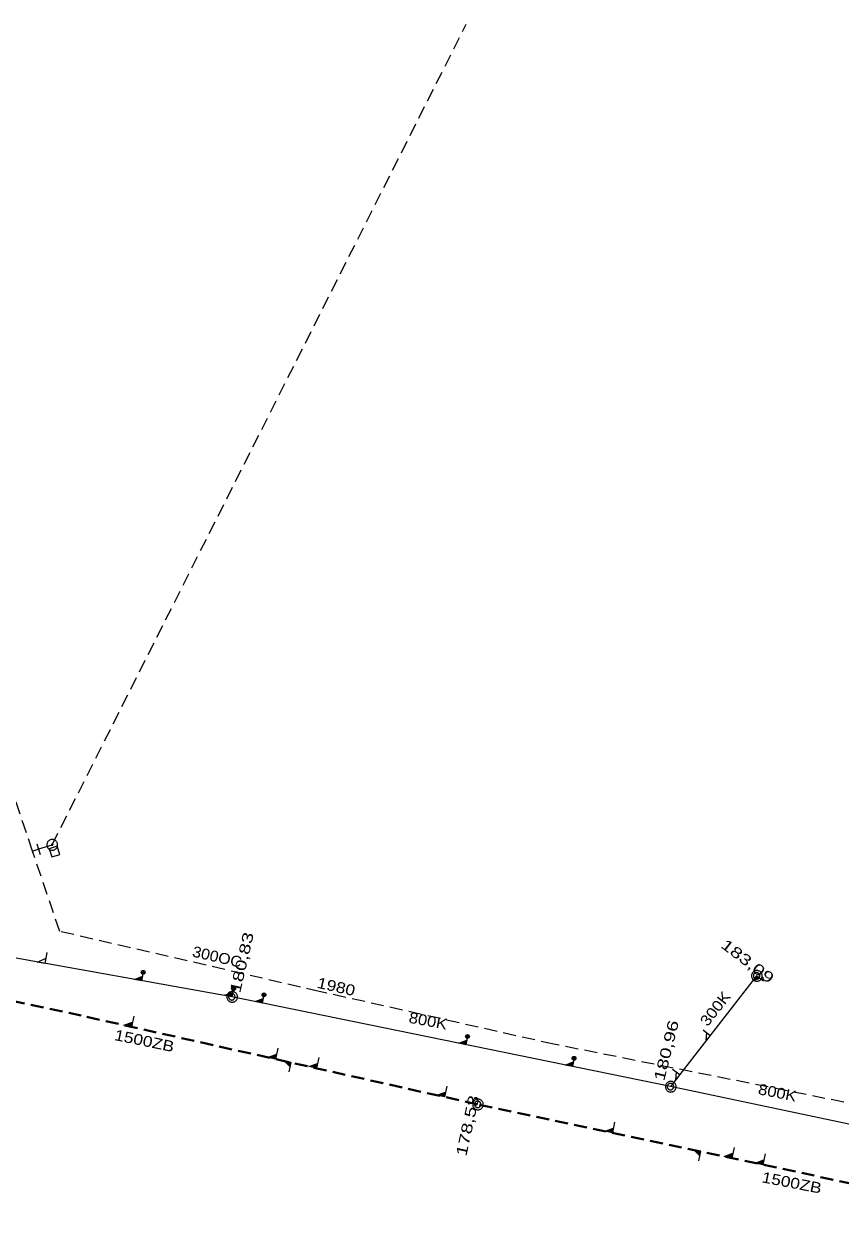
# Model space of a CAD drawing. Extents: x -740851 to -738888, y -1041382 to -1040235.
# Drawn here: x -740295.1 to -740219.2, y -1040431.1 to -1040319 of the extents above; entities that cross this region are included whole.
import ezdxf

# ---------------------------------------------------------------- set-up
doc = ezdxf.new("R2010")
doc.units = 0
doc.header["$LTSCALE"] = 0.4
doc.linetypes.add('MEDIUM_DASHED', pattern=[4.5, 3, -1.5])
for name, color, linetype, lineweight in [('18', 7, 'Continuous', 13), ('38', 7, 'Continuous', 13), ('39', 7, 'MEDIUM_DASHED', 13), ('8', 7, 'Continuous', 13)]:
    doc.layers.add(name, color=color, linetype=linetype, lineweight=lineweight)

msp = doc.modelspace()

# ---------------------------------------------------------------- linework, layer by layer
at = {"layer": '18', "lineweight": 25}
for p, q in [((-740275.79, -1040409.29), (-740318.03, -1040401.76)), ((-740227.03, -1040407.34), (-740235.03, -1040417.63)), ((-740235.03, -1040417.63), (-740275.79, -1040409.29)), ((-740216.38, -1040421.57), (-740235.03, -1040417.63))]:
    msp.add_line(p, q, dxfattribs=at)
at = {"layer": '18', "linetype": 'MEDIUM_DASHED', "lineweight": 40}
msp.add_line((-740197.01, -1040431.12), (-740252.95, -1040419.28), dxfattribs=at)
at = {"layer": '18'}
for points in [[(-740292.997, -1040405.188), (-740293.175, -1040406.188), (-740293.888, -1040406.061), (-740293.094, -1040405.737)], [(-740284.002, -1040406.841), (-740284.172, -1040407.793), (-740284.852, -1040407.672), (-740284.096, -1040407.364)], [(-740284.163, -1040407.45), (-740284.212, -1040407.728), (-740284.646, -1040407.65), (-740284.158, -1040407.451)], [(-740284.231, -1040407.541), (-740284.255, -1040407.68), (-740284.478, -1040407.64), (-740284.226, -1040407.542)], [(-740226.387, -1040407.84), (-740227.03, -1040407.34), (-740227.387, -1040407.799), (-740226.74, -1040407.566)], [(-740226.831, -1040407.549), (-740227.018, -1040407.404), (-740227.246, -1040407.697), (-740226.828, -1040407.546)], [(-740226.924, -1040407.53), (-740227.018, -1040407.458), (-740227.135, -1040407.608), (-740226.922, -1040407.527)], [(-740275.596, -1040408.356), (-740275.787, -1040409.288), (-740276.453, -1040409.152), (-740275.701, -1040408.868)], [(-740275.769, -1040408.951), (-740275.825, -1040409.223), (-740276.25, -1040409.136), (-740275.765, -1040408.952)], [(-740275.838, -1040409.039), (-740275.866, -1040409.175), (-740276.084, -1040409.13), (-740275.834, -1040409.04)], [(-740272.773, -1040408.933), (-740272.964, -1040409.866), (-740273.63, -1040409.73), (-740272.878, -1040409.445)], [(-740272.946, -1040409.529), (-740273.002, -1040409.8), (-740273.427, -1040409.713), (-740272.942, -1040409.53)], [(-740273.015, -1040409.617), (-740273.043, -1040409.752), (-740273.261, -1040409.708), (-740273.011, -1040409.618)], [(-740284.885, -1040411.083), (-740285.109, -1040412.083), (-740285.822, -1040411.923), (-740285.008, -1040411.632)], [(-740285.083, -1040411.72), (-740285.148, -1040412.011), (-740285.604, -1040411.909), (-740285.078, -1040411.721)], [(-740285.159, -1040411.813), (-740285.191, -1040411.959), (-740285.425, -1040411.907), (-740285.154, -1040411.814)], [(-740232.007, -1040412.355), (-740231.337, -1040412.876), (-740231.709, -1040413.355), (-740231.639, -1040412.641)], [(-740253.854, -1040412.804), (-740254.045, -1040413.737), (-740254.71, -1040413.601), (-740253.959, -1040413.316)], [(-740254.027, -1040413.4), (-740254.082, -1040413.671), (-740254.507, -1040413.584), (-740254.022, -1040413.401)], [(-740254.096, -1040413.488), (-740254.124, -1040413.623), (-740254.342, -1040413.579), (-740254.091, -1040413.489)], [(-740271.516, -1040414.074), (-740271.739, -1040415.074), (-740272.453, -1040414.914), (-740271.638, -1040414.623)], [(-740271.713, -1040414.711), (-740271.778, -1040415.002), (-740272.234, -1040414.9), (-740271.708, -1040414.712)], [(-740271.789, -1040414.804), (-740271.822, -1040414.95), (-740272.056, -1040414.898), (-740271.784, -1040414.806)], [(-740270.467, -1040416.267), (-740270.274, -1040415.404), (-740270.889, -1040415.267), (-740270.361, -1040415.793)], [(-740270.387, -1040415.697), (-740270.33, -1040415.446), (-740270.723, -1040415.358), (-740270.382, -1040415.698)], [(-740270.412, -1040415.596), (-740270.383, -1040415.47), (-740270.585, -1040415.425), (-740270.407, -1040415.597)], [(-740267.71, -1040414.925), (-740267.933, -1040415.925), (-740268.647, -1040415.766), (-740267.832, -1040415.474)], [(-740267.907, -1040415.563), (-740267.973, -1040415.854), (-740268.428, -1040415.752), (-740267.903, -1040415.564)], [(-740267.983, -1040415.656), (-740268.016, -1040415.802), (-740268.25, -1040415.749), (-740267.979, -1040415.657)], [(-740243.953, -1040414.83), (-740244.144, -1040415.763), (-740244.81, -1040415.627), (-740244.058, -1040415.342)], [(-740244.126, -1040415.426), (-740244.182, -1040415.697), (-740244.607, -1040415.61), (-740244.121, -1040415.426)], [(-740244.195, -1040415.514), (-740244.223, -1040415.649), (-740244.441, -1040415.605), (-740244.19, -1040415.514)], [(-740234.838, -1040415.996), (-740234.168, -1040416.517), (-740234.54, -1040416.996), (-740234.47, -1040416.282)], [(-740255.804, -1040417.589), (-740256.028, -1040418.589), (-740256.741, -1040418.429), (-740255.927, -1040418.138)], [(-740256.002, -1040418.226), (-740256.067, -1040418.517), (-740256.523, -1040418.415), (-740255.997, -1040418.227)], [(-740256.078, -1040418.32), (-740256.11, -1040418.465), (-740256.344, -1040418.413), (-740256.073, -1040418.321)], [(-740240.218, -1040420.928), (-740240.429, -1040421.928), (-740241.143, -1040421.777), (-740240.334, -1040421.477)], [(-740240.408, -1040421.566), (-740240.469, -1040421.857), (-740240.925, -1040421.76), (-740240.403, -1040421.567)], [(-740240.482, -1040421.66), (-740240.513, -1040421.805), (-740240.747, -1040421.756), (-740240.477, -1040421.661)], [(-740232.393, -1040424.539), (-740232.21, -1040423.67), (-740232.829, -1040423.539), (-740232.292, -1040424.062)], [(-740232.32, -1040423.965), (-740232.266, -1040423.712), (-740232.662, -1040423.628), (-740232.315, -1040423.966)], [(-740232.346, -1040423.864), (-740232.319, -1040423.738), (-740232.522, -1040423.695), (-740232.342, -1040423.865)], [(-740229.114, -1040423.278), (-740229.325, -1040424.278), (-740230.039, -1040424.127), (-740229.23, -1040423.827)], [(-740229.304, -1040423.916), (-740229.365, -1040424.207), (-740229.821, -1040424.111), (-740229.299, -1040423.917)], [(-740229.378, -1040424.01), (-740229.409, -1040424.155), (-740229.643, -1040424.106), (-740229.373, -1040424.011)], [(-740226.228, -1040423.889), (-740226.439, -1040424.889), (-740227.153, -1040424.738), (-740226.344, -1040424.438)], [(-740226.418, -1040424.527), (-740226.479, -1040424.818), (-740226.935, -1040424.721), (-740226.413, -1040424.528)], [(-740226.492, -1040424.621), (-740226.523, -1040424.766), (-740226.757, -1040424.717), (-740226.487, -1040424.622)]]:
    msp.add_lwpolyline(points, dxfattribs=at)
for points in [[(-740226.5, -1040407.35), (-740226.51, -1040407.3), (-740226.51, -1040407.25), (-740226.53, -1040407.2), (-740226.55, -1040407.15), (-740226.57, -1040407.1), (-740226.6, -1040407.06), (-740226.63, -1040407.02), (-740226.67, -1040406.98), (-740226.71, -1040406.95), (-740226.75, -1040406.92), (-740226.8, -1040406.9), (-740226.85, -1040406.88), (-740226.9, -1040406.86), (-740226.95, -1040406.86), (-740227, -1040406.85), (-740227.05, -1040406.86), (-740227.1, -1040406.86), (-740227.15, -1040406.88), (-740227.2, -1040406.9), (-740227.25, -1040406.92), (-740227.29, -1040406.95), (-740227.33, -1040406.98), (-740227.37, -1040407.02), (-740227.4, -1040407.06), (-740227.43, -1040407.1), (-740227.45, -1040407.15), (-740227.47, -1040407.2), (-740227.49, -1040407.25), (-740227.49, -1040407.3), (-740227.5, -1040407.35), (-740227.49, -1040407.4), (-740227.49, -1040407.45), (-740227.47, -1040407.5), (-740227.45, -1040407.55), (-740227.43, -1040407.6), (-740227.4, -1040407.64), (-740227.37, -1040407.68), (-740227.33, -1040407.72), (-740227.29, -1040407.75), (-740227.25, -1040407.78), (-740227.2, -1040407.8), (-740227.15, -1040407.82), (-740227.1, -1040407.84), (-740227.05, -1040407.84), (-740227, -1040407.85), (-740226.95, -1040407.84), (-740226.9, -1040407.84), (-740226.85, -1040407.82), (-740226.8, -1040407.8), (-740226.75, -1040407.78), (-740226.71, -1040407.75), (-740226.67, -1040407.72), (-740226.63, -1040407.68), (-740226.6, -1040407.64), (-740226.57, -1040407.6), (-740226.55, -1040407.55), (-740226.53, -1040407.5), (-740226.51, -1040407.45), (-740226.51, -1040407.4)], [(-740226.73, -1040407.34), (-740226.73, -1040407.31), (-740226.736, -1040407.28), (-740226.742, -1040407.25), (-740226.754, -1040407.22), (-740226.772, -1040407.19), (-740226.79, -1040407.166), (-740226.808, -1040407.142), (-740226.832, -1040407.118), (-740226.856, -1040407.1), (-740226.88, -1040407.082), (-740226.91, -1040407.064), (-740226.94, -1040407.052), (-740226.97, -1040407.046), (-740227, -1040407.04), (-740227.03, -1040407.04), (-740227.06, -1040407.04), (-740227.09, -1040407.046), (-740227.12, -1040407.052), (-740227.15, -1040407.064), (-740227.18, -1040407.082), (-740227.204, -1040407.1), (-740227.228, -1040407.118), (-740227.252, -1040407.142), (-740227.27, -1040407.166), (-740227.288, -1040407.19), (-740227.306, -1040407.22), (-740227.318, -1040407.25), (-740227.324, -1040407.28), (-740227.33, -1040407.31), (-740227.33, -1040407.34), (-740227.33, -1040407.37), (-740227.324, -1040407.4), (-740227.318, -1040407.43), (-740227.306, -1040407.46), (-740227.288, -1040407.49), (-740227.27, -1040407.514), (-740227.252, -1040407.538), (-740227.228, -1040407.562), (-740227.204, -1040407.58), (-740227.18, -1040407.598), (-740227.15, -1040407.616), (-740227.12, -1040407.628), (-740227.09, -1040407.634), (-740227.06, -1040407.64), (-740227.03, -1040407.64), (-740227, -1040407.64), (-740226.97, -1040407.634), (-740226.94, -1040407.628), (-740226.91, -1040407.616), (-740226.88, -1040407.598), (-740226.856, -1040407.58), (-740226.832, -1040407.562), (-740226.808, -1040407.538), (-740226.79, -1040407.514), (-740226.772, -1040407.49), (-740226.754, -1040407.46), (-740226.742, -1040407.43), (-740226.736, -1040407.4), (-740226.73, -1040407.37)], [(-740275.26, -1040409.3), (-740275.27, -1040409.25), (-740275.27, -1040409.2), (-740275.29, -1040409.15), (-740275.31, -1040409.1), (-740275.33, -1040409.05), (-740275.36, -1040409.01), (-740275.39, -1040408.97), (-740275.43, -1040408.93), (-740275.47, -1040408.9), (-740275.51, -1040408.87), (-740275.56, -1040408.85), (-740275.61, -1040408.83), (-740275.66, -1040408.81), (-740275.71, -1040408.81), (-740275.76, -1040408.8), (-740275.81, -1040408.81), (-740275.86, -1040408.81), (-740275.91, -1040408.83), (-740275.96, -1040408.85), (-740276.01, -1040408.87), (-740276.05, -1040408.9), (-740276.09, -1040408.93), (-740276.13, -1040408.97), (-740276.16, -1040409.01), (-740276.19, -1040409.05), (-740276.21, -1040409.1), (-740276.23, -1040409.15), (-740276.25, -1040409.2), (-740276.25, -1040409.25), (-740276.26, -1040409.3), (-740276.25, -1040409.35), (-740276.25, -1040409.4), (-740276.23, -1040409.45), (-740276.21, -1040409.5), (-740276.19, -1040409.55), (-740276.16, -1040409.59), (-740276.13, -1040409.63), (-740276.09, -1040409.67), (-740276.05, -1040409.7), (-740276.01, -1040409.73), (-740275.96, -1040409.75), (-740275.91, -1040409.77), (-740275.86, -1040409.79), (-740275.81, -1040409.79), (-740275.76, -1040409.8), (-740275.71, -1040409.79), (-740275.66, -1040409.79), (-740275.61, -1040409.77), (-740275.56, -1040409.75), (-740275.51, -1040409.73), (-740275.47, -1040409.7), (-740275.43, -1040409.67), (-740275.39, -1040409.63), (-740275.36, -1040409.59), (-740275.33, -1040409.55), (-740275.31, -1040409.5), (-740275.29, -1040409.45), (-740275.27, -1040409.4), (-740275.27, -1040409.35)], [(-740275.49, -1040409.29), (-740275.49, -1040409.26), (-740275.496, -1040409.23), (-740275.502, -1040409.2), (-740275.514, -1040409.17), (-740275.532, -1040409.14), (-740275.55, -1040409.116), (-740275.568, -1040409.092), (-740275.592, -1040409.068), (-740275.616, -1040409.05), (-740275.64, -1040409.032), (-740275.67, -1040409.014), (-740275.7, -1040409.002), (-740275.73, -1040408.996), (-740275.76, -1040408.99), (-740275.79, -1040408.99), (-740275.82, -1040408.99), (-740275.85, -1040408.996), (-740275.88, -1040409.002), (-740275.91, -1040409.014), (-740275.94, -1040409.032), (-740275.964, -1040409.05), (-740275.988, -1040409.068), (-740276.012, -1040409.092), (-740276.03, -1040409.116), (-740276.048, -1040409.14), (-740276.066, -1040409.17), (-740276.078, -1040409.2), (-740276.084, -1040409.23), (-740276.09, -1040409.26), (-740276.09, -1040409.29), (-740276.09, -1040409.32), (-740276.084, -1040409.35), (-740276.078, -1040409.38), (-740276.066, -1040409.41), (-740276.048, -1040409.44), (-740276.03, -1040409.464), (-740276.012, -1040409.488), (-740275.988, -1040409.512), (-740275.964, -1040409.53), (-740275.94, -1040409.548), (-740275.91, -1040409.566), (-740275.88, -1040409.578), (-740275.85, -1040409.584), (-740275.82, -1040409.59), (-740275.79, -1040409.59), (-740275.76, -1040409.59), (-740275.73, -1040409.584), (-740275.7, -1040409.578), (-740275.67, -1040409.566), (-740275.64, -1040409.548), (-740275.616, -1040409.53), (-740275.592, -1040409.512), (-740275.568, -1040409.488), (-740275.55, -1040409.464), (-740275.532, -1040409.44), (-740275.514, -1040409.41), (-740275.502, -1040409.38), (-740275.496, -1040409.35), (-740275.49, -1040409.32)], [(-740234.5, -1040417.64), (-740234.51, -1040417.59), (-740234.51, -1040417.54), (-740234.53, -1040417.49), (-740234.55, -1040417.44), (-740234.57, -1040417.39), (-740234.6, -1040417.35), (-740234.63, -1040417.31), (-740234.67, -1040417.27), (-740234.71, -1040417.24), (-740234.75, -1040417.21), (-740234.8, -1040417.19), (-740234.85, -1040417.17), (-740234.9, -1040417.15), (-740234.95, -1040417.15), (-740235, -1040417.14), (-740235.05, -1040417.15), (-740235.1, -1040417.15), (-740235.15, -1040417.17), (-740235.2, -1040417.19), (-740235.25, -1040417.21), (-740235.29, -1040417.24), (-740235.33, -1040417.27), (-740235.37, -1040417.31), (-740235.4, -1040417.35), (-740235.43, -1040417.39), (-740235.45, -1040417.44), (-740235.47, -1040417.49), (-740235.49, -1040417.54), (-740235.49, -1040417.59), (-740235.5, -1040417.64), (-740235.49, -1040417.69), (-740235.49, -1040417.74), (-740235.47, -1040417.79), (-740235.45, -1040417.84), (-740235.43, -1040417.89), (-740235.4, -1040417.93), (-740235.37, -1040417.97), (-740235.33, -1040418.01), (-740235.29, -1040418.04), (-740235.25, -1040418.07), (-740235.2, -1040418.09), (-740235.15, -1040418.11), (-740235.1, -1040418.13), (-740235.05, -1040418.13), (-740235, -1040418.14), (-740234.95, -1040418.13), (-740234.9, -1040418.13), (-740234.85, -1040418.11), (-740234.8, -1040418.09), (-740234.75, -1040418.07), (-740234.71, -1040418.04), (-740234.67, -1040418.01), (-740234.63, -1040417.97), (-740234.6, -1040417.93), (-740234.57, -1040417.89), (-740234.55, -1040417.84), (-740234.53, -1040417.79), (-740234.51, -1040417.74), (-740234.51, -1040417.69)], [(-740234.73, -1040417.63), (-740234.73, -1040417.6), (-740234.736, -1040417.57), (-740234.742, -1040417.54), (-740234.754, -1040417.51), (-740234.772, -1040417.48), (-740234.79, -1040417.456), (-740234.808, -1040417.432), (-740234.832, -1040417.408), (-740234.856, -1040417.39), (-740234.88, -1040417.372), (-740234.91, -1040417.354), (-740234.94, -1040417.342), (-740234.97, -1040417.336), (-740235, -1040417.33), (-740235.03, -1040417.33), (-740235.06, -1040417.33), (-740235.09, -1040417.336), (-740235.12, -1040417.342), (-740235.15, -1040417.354), (-740235.18, -1040417.372), (-740235.204, -1040417.39), (-740235.228, -1040417.408), (-740235.252, -1040417.432), (-740235.27, -1040417.456), (-740235.288, -1040417.48), (-740235.306, -1040417.51), (-740235.318, -1040417.54), (-740235.324, -1040417.57), (-740235.33, -1040417.6), (-740235.33, -1040417.63), (-740235.33, -1040417.66), (-740235.324, -1040417.69), (-740235.318, -1040417.72), (-740235.306, -1040417.75), (-740235.288, -1040417.78), (-740235.27, -1040417.804), (-740235.252, -1040417.828), (-740235.228, -1040417.852), (-740235.204, -1040417.87), (-740235.18, -1040417.888), (-740235.15, -1040417.906), (-740235.12, -1040417.918), (-740235.09, -1040417.924), (-740235.06, -1040417.93), (-740235.03, -1040417.93), (-740235, -1040417.93), (-740234.97, -1040417.924), (-740234.94, -1040417.918), (-740234.91, -1040417.906), (-740234.88, -1040417.888), (-740234.856, -1040417.87), (-740234.832, -1040417.852), (-740234.808, -1040417.828), (-740234.79, -1040417.804), (-740234.772, -1040417.78), (-740234.754, -1040417.75), (-740234.742, -1040417.72), (-740234.736, -1040417.69), (-740234.73, -1040417.66)], [(-740252.42, -1040419.29), (-740252.43, -1040419.24), (-740252.43, -1040419.19), (-740252.45, -1040419.14), (-740252.47, -1040419.09), (-740252.49, -1040419.04), (-740252.52, -1040419), (-740252.55, -1040418.96), (-740252.59, -1040418.92), (-740252.63, -1040418.89), (-740252.67, -1040418.86), (-740252.72, -1040418.84), (-740252.77, -1040418.82), (-740252.82, -1040418.8), (-740252.87, -1040418.8), (-740252.92, -1040418.79), (-740252.97, -1040418.8), (-740253.02, -1040418.8), (-740253.07, -1040418.82), (-740253.12, -1040418.84), (-740253.17, -1040418.86), (-740253.21, -1040418.89), (-740253.25, -1040418.92), (-740253.29, -1040418.96), (-740253.32, -1040419), (-740253.35, -1040419.04), (-740253.37, -1040419.09), (-740253.39, -1040419.14), (-740253.41, -1040419.19), (-740253.41, -1040419.24), (-740253.42, -1040419.29), (-740253.41, -1040419.34), (-740253.41, -1040419.39), (-740253.39, -1040419.44), (-740253.37, -1040419.49), (-740253.35, -1040419.54), (-740253.32, -1040419.58), (-740253.29, -1040419.62), (-740253.25, -1040419.66), (-740253.21, -1040419.69), (-740253.17, -1040419.72), (-740253.12, -1040419.74), (-740253.07, -1040419.76), (-740253.02, -1040419.78), (-740252.97, -1040419.78), (-740252.92, -1040419.79), (-740252.87, -1040419.78), (-740252.82, -1040419.78), (-740252.77, -1040419.76), (-740252.72, -1040419.74), (-740252.67, -1040419.72), (-740252.63, -1040419.69), (-740252.59, -1040419.66), (-740252.55, -1040419.62), (-740252.52, -1040419.58), (-740252.49, -1040419.54), (-740252.47, -1040419.49), (-740252.45, -1040419.44), (-740252.43, -1040419.39), (-740252.43, -1040419.34)], [(-740252.65, -1040419.28), (-740252.65, -1040419.25), (-740252.656, -1040419.22), (-740252.662, -1040419.19), (-740252.674, -1040419.16), (-740252.692, -1040419.13), (-740252.71, -1040419.106), (-740252.728, -1040419.082), (-740252.752, -1040419.058), (-740252.776, -1040419.04), (-740252.8, -1040419.022), (-740252.83, -1040419.004), (-740252.86, -1040418.992), (-740252.89, -1040418.986), (-740252.92, -1040418.98), (-740252.95, -1040418.98), (-740252.98, -1040418.98), (-740253.01, -1040418.986), (-740253.04, -1040418.992), (-740253.07, -1040419.004), (-740253.1, -1040419.022), (-740253.124, -1040419.04), (-740253.148, -1040419.058), (-740253.172, -1040419.082), (-740253.19, -1040419.106), (-740253.208, -1040419.13), (-740253.226, -1040419.16), (-740253.238, -1040419.19), (-740253.244, -1040419.22), (-740253.25, -1040419.25), (-740253.25, -1040419.28), (-740253.25, -1040419.31), (-740253.244, -1040419.34), (-740253.238, -1040419.37), (-740253.226, -1040419.4), (-740253.208, -1040419.43), (-740253.19, -1040419.454), (-740253.172, -1040419.478), (-740253.148, -1040419.502), (-740253.124, -1040419.52), (-740253.1, -1040419.538), (-740253.07, -1040419.556), (-740253.04, -1040419.568), (-740253.01, -1040419.574), (-740252.98, -1040419.58), (-740252.95, -1040419.58), (-740252.92, -1040419.58), (-740252.89, -1040419.574), (-740252.86, -1040419.568), (-740252.83, -1040419.556), (-740252.8, -1040419.538), (-740252.776, -1040419.52), (-740252.752, -1040419.502), (-740252.728, -1040419.478), (-740252.71, -1040419.454), (-740252.692, -1040419.43), (-740252.674, -1040419.4), (-740252.662, -1040419.37), (-740252.656, -1040419.34), (-740252.65, -1040419.31)]]:
    msp.add_lwpolyline(points, close=True, dxfattribs=at)
at = {"layer": '18', "linetype": 'MEDIUM_DASHED', "lineweight": 40}
msp.add_lwpolyline([(-740252.95, -1040419.28), (-740289.78, -1040411.04), (-740299.021, -1040409.066), (-740306.23, -1040407.14)], dxfattribs=at)
at = {"layer": '18'}
for centre, radius in [((-740284.034, -1040407.016), 0.182), ((-740284.035, -1040407.015), 0.0901), ((-740275.632, -1040408.527), 0.179), ((-740275.633, -1040408.526), 0.0886), ((-740272.809, -1040409.105), 0.179), ((-740272.809, -1040409.103), 0.0886), ((-740253.89, -1040412.976), 0.179), ((-740253.89, -1040412.974), 0.0886), ((-740243.989, -1040415.002), 0.179), ((-740243.989, -1040415), 0.0886)]:
    msp.add_circle(centre, radius, dxfattribs=at)
at = {"layer": '38'}
for p, q in [((-740294.311, -1040395.753), (-740293.74, -1040395.56)), ((-740293.74, -1040395.56), (-740292.49, -1040395.17))]:
    msp.add_line(p, q, dxfattribs=at)
at = {"layer": '39'}
msp.add_line((-740292.49, -1040395.17), (-740254.007, -1040318.954), dxfattribs=at)
at = {"layer": '8'}
for p, q in [((-740293.558, -1040396.1), (-740293.896, -1040395.1)), ((-740292.539, -1040395.219), (-740292.439, -1040395.119)), ((-740292.539, -1040395.119), (-740292.439, -1040395.219)), ((-740292.539, -1040395.119), (-740292.539, -1040395.139)), ((-740292.539, -1040395.119), (-740292.519, -1040395.119)), ((-740292.539, -1040395.219), (-740292.539, -1040395.199)), ((-740292.539, -1040395.219), (-740292.519, -1040395.219)), ((-740292.439, -1040395.119), (-740292.459, -1040395.119)), ((-740292.439, -1040395.219), (-740292.459, -1040395.219)), ((-740292.439, -1040395.119), (-740292.439, -1040395.139)), ((-740292.439, -1040395.219), (-740292.439, -1040395.199))]:
    msp.add_line(p, q, dxfattribs=at)
at = {"layer": '8', "linetype": 'MEDIUM_DASHED', "lineweight": 25}
msp.add_lwpolyline([(-740213.61, -1040420.13), (-740245.88, -1040413.69), (-740267.67, -1040408.79), (-740291.79, -1040403.21), (-740294.311, -1040395.753), (-740297.337, -1040386.803)], dxfattribs=at)
at = {"layer": '8'}
for points in [[(-740292.001, -1040395.027), (-740292.025, -1040394.982), (-740292.04, -1040394.934), (-740292.074, -1040394.892), (-740292.108, -1040394.85), (-740292.143, -1040394.808), (-740292.183, -1040394.779), (-740292.224, -1040394.75), (-740292.274, -1040394.723), (-740292.322, -1040394.706), (-740292.369, -1040394.69), (-740292.423, -1040394.685), (-740292.477, -1040394.681), (-740292.531, -1040394.677), (-740292.579, -1040394.692), (-740292.63, -1040394.697), (-740292.675, -1040394.722), (-740292.723, -1040394.737), (-740292.765, -1040394.771), (-740292.807, -1040394.805), (-740292.849, -1040394.839), (-740292.878, -1040394.88), (-740292.908, -1040394.921), (-740292.934, -1040394.971), (-740292.951, -1040395.018), (-740292.968, -1040395.066), (-740292.972, -1040395.12), (-740292.976, -1040395.174), (-740292.98, -1040395.228), (-740292.965, -1040395.276), (-740292.96, -1040395.327), (-740292.935, -1040395.372), (-740292.92, -1040395.42), (-740292.886, -1040395.461), (-740292.852, -1040395.503), (-740292.818, -1040395.545), (-740292.777, -1040395.575), (-740292.736, -1040395.604), (-740292.686, -1040395.631), (-740292.639, -1040395.647), (-740292.591, -1040395.664), (-740292.537, -1040395.668), (-740292.483, -1040395.673), (-740292.429, -1040395.677), (-740292.382, -1040395.662), (-740292.331, -1040395.657), (-740292.286, -1040395.632), (-740292.238, -1040395.617), (-740292.196, -1040395.583), (-740292.154, -1040395.549), (-740292.112, -1040395.515), (-740292.082, -1040395.474), (-740292.053, -1040395.433), (-740292.027, -1040395.383), (-740292.01, -1040395.335), (-740291.993, -1040395.288), (-740291.989, -1040395.234), (-740291.984, -1040395.18), (-740291.98, -1040395.126), (-740291.995, -1040395.078)], [(-740292.533, -1040396.299), (-740291.771, -1040396.061), (-740292.009, -1040395.299), (-740292.771, -1040395.537)], [(-740292.439, -1040395.169), (-740292.439, -1040395.164), (-740292.44, -1040395.159), (-740292.441, -1040395.154), (-740292.443, -1040395.149), (-740292.446, -1040395.144), (-740292.449, -1040395.14), (-740292.452, -1040395.136), (-740292.456, -1040395.132), (-740292.46, -1040395.129), (-740292.464, -1040395.126), (-740292.469, -1040395.123), (-740292.474, -1040395.121), (-740292.479, -1040395.12), (-740292.484, -1040395.119), (-740292.489, -1040395.119), (-740292.494, -1040395.119), (-740292.499, -1040395.12), (-740292.504, -1040395.121), (-740292.509, -1040395.123), (-740292.514, -1040395.126), (-740292.518, -1040395.129), (-740292.522, -1040395.132), (-740292.526, -1040395.136), (-740292.529, -1040395.14), (-740292.532, -1040395.144), (-740292.535, -1040395.149), (-740292.537, -1040395.154), (-740292.538, -1040395.159), (-740292.539, -1040395.164), (-740292.539, -1040395.169), (-740292.539, -1040395.174), (-740292.538, -1040395.179), (-740292.537, -1040395.184), (-740292.535, -1040395.189), (-740292.532, -1040395.194), (-740292.529, -1040395.198), (-740292.526, -1040395.202), (-740292.522, -1040395.206), (-740292.518, -1040395.209), (-740292.514, -1040395.212), (-740292.509, -1040395.215), (-740292.504, -1040395.217), (-740292.499, -1040395.218), (-740292.494, -1040395.219), (-740292.489, -1040395.219), (-740292.484, -1040395.219), (-740292.479, -1040395.218), (-740292.474, -1040395.217), (-740292.469, -1040395.215), (-740292.464, -1040395.212), (-740292.46, -1040395.209), (-740292.456, -1040395.206), (-740292.452, -1040395.202), (-740292.449, -1040395.198), (-740292.446, -1040395.194), (-740292.443, -1040395.189), (-740292.441, -1040395.184), (-740292.44, -1040395.179), (-740292.439, -1040395.174)]]:
    msp.add_lwpolyline(points, close=True, dxfattribs=at)

# ---------------------------------------------------------------- texts
at = {"layer": '18'}
for s, rotation, width, p in [('180,83', 76.99, 1.4, (-740275.028, -1040409.006)), ('183,09', 322.597, 1.4, (-740230.435, -1040404.64)), ('300K', 51.989, 1.15, (-740231.582, -1040412.114)), ('800K', 349.451, 1.15, (-740259.412, -1040411.683)), ('1500ZB', 348.39, 1.2, (-740286.77, -1040413.297)), ('180,96', 75.99, 1.4, (-740235.622, -1040417.171)), ('800K', 348.7, 1.15, (-740226.948, -1040418.325)), ('178,53', 77.749, 1.4, (-740254.008, -1040424.159)), ('1500ZB', 349.049, 1.2, (-740226.607, -1040426.509))]:
    msp.add_text(s, height=1, rotation=rotation, dxfattribs=dict(at, width=width)).set_placement(p)
at = {"layer": '8'}
for s, rotation, width, p in [('300OC', 346.974, 1.1, (-740279.538, -1040405.536)), ('1980', 347.327, 1.2, (-740267.944, -1040408.44))]:
    msp.add_text(s, height=1, rotation=rotation, dxfattribs=dict(at, width=width)).set_placement(p)

doc.saveas('drawing.dxf')
